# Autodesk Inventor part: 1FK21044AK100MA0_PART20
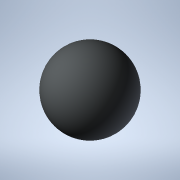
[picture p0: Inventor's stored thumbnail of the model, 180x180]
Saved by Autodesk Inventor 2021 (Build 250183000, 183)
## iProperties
Created: 2025-04
Part Number: 1FK21044AK100MA0_PART20
Material: Generic
Catalog Web Link: www.3dfindit.com
Description: -Servo synchronous motor
Document SubType Name: Modeling
Designer: psAdmin
Mass: 0.137258 g
Surface Area: 1.2868 cm^2
Volume: 0.137258 cm^3
Density: 1 g/cm^3
Appearance: PSOLRGB-212-217-219
Category: PARTsolutions
Title: 1FK21044AK100MA0_PART20
Author: Cadenas PARTsolutions
Comments: Servo synchronous motor
Sending System: PARTsolutions
Preprocessor: ST-DEVELOPER v19.3
PSOL_IDENT_0: {$CADENAS_DATA/23d-libs/siemens_ag/_cat_/5e/d8/1fk21044ak100ma0.prj},216 {VTYP=3D},{NB=1FK21044AK100
PSOL_IDENT_1: MA0_PART20},{LINA=1FK21044AK100MA0_PART20},{NN=1FK21044AK100MA0_PART20},{NOPRJ=TRUE},{DATE=19.08.202
PSOL_IDENT_2: 5 14:00:41},{GEOMDATE=30.07.2025 02:00:53},{VERSION=},{LINEID=10},{WBVAR=},{WBNUMERIC=}  {NB=1FK2104
PSOL_IDENT_3: 4AK100MA0_PART20},{LINA=1FK21044AK100MA0_PART20},{KT=DUMMY},{PREVIEW=../../../_pool_/cb/72/p_d211_xx
PSOL_IDENT_4: _00434j.png},{DESCSHORT=SIMOTICS S-1FK2 HD, SINAMICS S210 3AC 400V-480V, 0.95 Nm, 6000 rpm},{DESCLON
PSOL_IDENT_5: G=SIMOTICS S-1FK2 HD servo motor M0=1.27 Nm; PN = 0.6 kW at nN=6000 rpm (380-480 V); PN = 0.4 kW at
PSOL_IDENT_6: nN=3000 rpm (200-240 V); with holding brake; degree of protection IP64; cylindrical shaft D19x40mm;
PSOL_IDENT_7: absolute encoder 22-bit + 12-bit multiturn (encoder AM22DQC); with OCC interface; plug size M17, rot
PSOL_IDENT_8: atable; SIMOTICS S-1FK2 servomotorfor a wide range of uses in industrial environments. SIMOTICS S‑1F
PSOL_IDENT_9: K2 servomotors are compact synchronous motors with a high dynamic performance that set themselves ap
PSOL_IDENT_10: art as a result of their high power density, degree of protection and overload capability. The motor
PSOL_IDENT_11: s are available in two variants: as High Dynamic variant (highest dynamic performance as a result of
PSOL_IDENT_12: the low intrinsic moment of inertia for applications demanding a high dynamic performance with low
PSOL_IDENT_13: moved masses) - and as Compact variant (precise and stable closed-loop control for medium up to larg
PSOL_IDENT_14: e moved masses as a result of a medium intrinsic moment of inertia). SIMOTICSS‑1FK2 servomotors full
PSOL_IDENT_15: y exploit their strengths in a system with the SINAMICSS210 frequency converter and simple connectio
PSOL_IDENT_16: n using the one cable connection (OCC). Advantages include the short control and positioning times,
PSOL_IDENT_17: fast and precise correction of disturbing quantities as well as stable control with a high dynamic p
PSOL_IDENT_18: erformance. The servo motors can be configured to address a wide range of requirements. For example
PSOL_IDENT_19: with and without holding brake, IP64 or IP65 degree of protection, singleturn or multiturn absolute
PSOL_IDENT_20: encoders - to name just a few. Further, the servomotors are available in different shaft heights ext
PSOL_IDENT_21: ending from 20 to 100. A shaft sealing ring is available to achieve an IP65 degree of protection and
PSOL_IDENT_22: for subsequent mounting at the motor or as spare part. SIMOTICS - the optimum motor for each and ev
PSOL_IDENT_23: ery motion control application.},{INTNO=804766910005},{SUPPLIERALTNO=1FK2104-4AK10-0MA0},{MANUID=1FK
PSOL_IDENT_24: 21044AK100MA0},{MANUNAME=Siemens},{MANUTYPEDESC=Synchronous motor 1FK2-HD 1,27 Nm},{AAU732=SIMOTICS}
PSOL_IDENT_25: ,{AAO057=S-1FK2},{AAU734=SIMOTICS S-1FK2 HD servo motor M0=1.27 Nm; PN = 0.6 kW at nN=6000 rpm (380-
PSOL_IDENT_26: 480 V); PN = 0.4 kW at nN=3000 rpm (200-240 V); with holding brake; degree of protection IP64; cylin
PSOL_IDENT_27: drical shaft D19x40mm; absolute encoder 22-bit + 12-bit multiturn (encoder AM22DQC); with OCC interf
PSOL_IDENT_28: ace; plug size M17, rotatable;},{AAW338=Synchronous motor 1FK2-HD 1,27 Nm},{AAO742=SIMOTICS},{AAO663=
PSOL_IDENT_29: 4042948691076},{NOCUPEROU=1},{PRICEQUANTITY=1},{QUANTITYMIN=1},{QUANTITYINT=1},{CTN=85015100},{COO=D
PSOL_IDENT_30: E},{AAO676=1FK2104-4AK10-0MA0},{AAO677=Siemens AG},{ORDERUNIT=C62},{CONTENTUNIT=C62}
NB: 1FK21044AK100MA0_PART20
NT: Servo synchronous motor
NBSYN: $MANUID._PART20
LINA: 1FK21044AK100MA0_PART20
CATALOG: SIEMENS
PREVIEW: ../../../_pool_/cb/72/p_d211_xx_00434j.png
DESCSHORT: SIMOTICS S-1FK2 HD, SINAMICS S210 3AC 400V-480V, 0.95 Nm, 6000 rpm
DESCLONG: SIMOTICS S-1FK2 HD servo motor M0=1.27 Nm; PN = 0.6 kW at nN=6000 rpm (380-480 V); PN = 0.4 kW at nN=3000 rpm (200-240 V); with holding brake; degree of protect
INTNO: 804766910005
SUPPLIERALTNO: 1FK2104-4AK10-0MA0
MANUID: 1FK21044AK100MA0
MANUNAME: Siemens
MANUTYPEDESC: Synchronous motor 1FK2-HD 1,27 Nm
AAU732: SIMOTICS
AAO057: S-1FK2
AAU734: SIMOTICS S-1FK2 HD servo motor M0=1.27 Nm; PN = 0.6 kW at nN=6000 rpm (380-480 V); PN = 0.4 kW at nN=3000 rpm (200-240 V); with holding brake; degree of protect
AAW338: Synchronous motor 1FK2-HD 1,27 Nm
AAO742: SIMOTICS
AAO663: 4042948691076.0
NOCUPEROU: 1
PRICEQUANTITY: 1
QUANTITYMIN: 1
QUANTITYINT: 1
CTN: 85015100
COO: DE
ARTICLENO: 1FK21044AK100MA0_PART20
BOMINFO: 1FK21044AK100MA0_PART20
CREATOR: CADENAS GmbH
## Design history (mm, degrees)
feature "2025_04_17_15_35_41_0968"
body "Solid1"
